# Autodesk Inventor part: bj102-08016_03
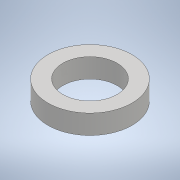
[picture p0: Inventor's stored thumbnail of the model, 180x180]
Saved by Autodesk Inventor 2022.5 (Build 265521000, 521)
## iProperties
Part Number: bj102-08016_03
Material: 一般
Document SubType Name: Modeling
Designer: ImaoCorp
Density: 1 g/cm^3
Appearance: 既定
Author: ImaoCorp
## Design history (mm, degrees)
feature "bj102-08016_03"
node "ソリッド1"
